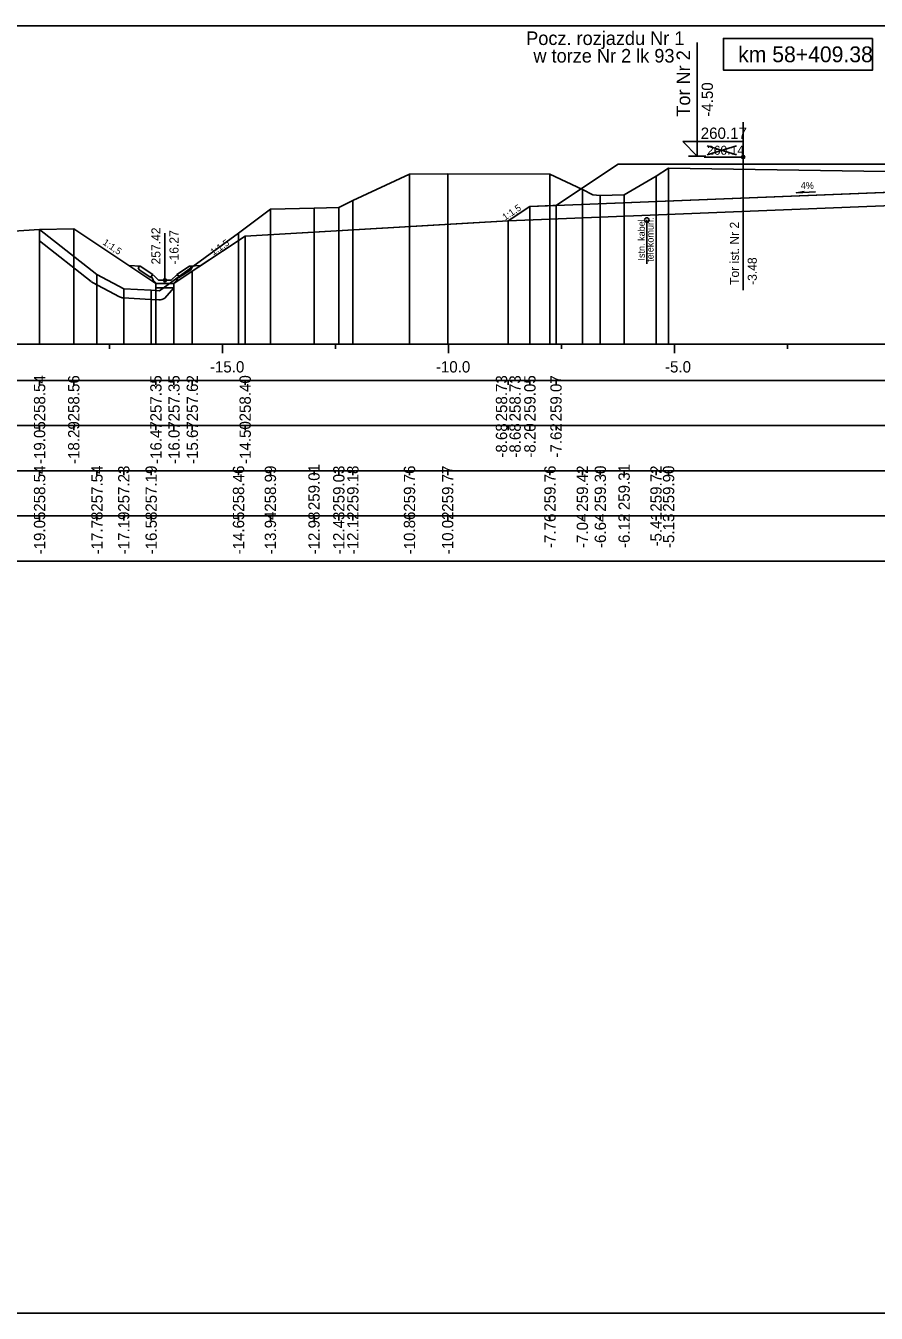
# Model space of a CAD drawing. Extents: x 6516023 to 6560129, y 5513077 to 5529206.
# Drawn here: x 6516540.36 to 6516559.18, y 5514451.16 to 5514479.66 of the extents above; entities that cross this region are included whole.
import ezdxf

# ---------------------------------------------------------------- set-up
doc = ezdxf.new("R2010")
doc.units = 0
for name, color, linetype in [('IR_default', 7, 'Continuous'), ('TOR_PRZEK_P-kable', 7, 'Continuous'), ('TOR_PRZEK_P-komponent', 7, 'Continuous'), ('TOR_PRZEK_P-odwodnienie', 7, 'Continuous'), ('TOR_PRZEK_P-opisy', 7, 'Continuous'), ('TOR_PRZEK_P-schodkowanie+wymiana', 7, 'Continuous'), ('TOR_PRZEK_P-tabelka istniejace', 7, 'Continuous'), ('TOR_PRZEK_P-tabelka projektowane', 7, 'Continuous'), ('TOR_PRZEK_P-teren istniejacy', 7, 'Continuous'), ('TOR_PRZEK_P-tory istniejace', 7, 'Continuous'), ('TOR_PRZEK_P-tory projektowane', 7, 'Continuous'), ('TOR_PRZEK_P-uklad odniesienia', 7, 'Continuous'), ('TOR_PRZEK_P-warstwa ochronna I', 7, 'Continuous'), ('TOR_PRZEK_P-warstwa ochronna II', 7, 'Continuous'), ('TOR_RAMKI-ramka+tabelka 1', 7, 'Continuous')]:
    doc.layers.add(name, color=color, linetype=linetype)

msp = doc.modelspace()

# ---------------------------------------------------------------- linework, layer by layer
at = {"layer": 'IR_default'}
msp.add_lwpolyline([(6516540.664, 5514475.149), (6516541.42, 5514475.164), (6516543.238, 5514473.952), (6516543.288, 5514473.952), (6516543.638, 5514473.952), (6516543.688, 5514473.985), (6516544.043, 5514474.222), (6516544.19, 5514474.32), (6516545.213, 5514475.002), (6516550.135, 5514475.283), (6516551.034, 5514475.335), (6516551.434, 5514475.601), (6516551.513, 5514475.654), (6516552.019, 5514475.674), (6516552.091, 5514475.677), (6516553.293, 5514476.479), (6516553.463, 5514476.592), (6516554.073, 5514476.592), (6516554.159, 5514476.592), (6516555.082, 5514476.592), (6516555.213, 5514476.592), (6516556.746, 5514476.592), (6516556.963, 5514476.592), (6516557.839, 5514476.592), (6516557.963, 5514476.592), (6516559.496, 5514476.592)], dxfattribs=at)
at = {"layer": 'TOR_PRZEK_P-kable'}
msp.add_line((6516554.101, 5514475.357), (6516554.101, 5514474.383), dxfattribs=at)
msp.add_circle((6516554.101, 5514475.357), 0.05, dxfattribs=at)
at = {"layer": 'TOR_PRZEK_P-komponent'}
msp.add_lwpolyline([(6516553.463, 5514476.592), (6516555.213, 5514476.592), (6516554.159, 5514476.592), (6516556.963, 5514476.592), (6516557.963, 5514476.592), (6516559.713, 5514476.592), (6516561.463, 5514476.592), (6516562.013, 5514476.593), (6516563.763, 5514476.593), (6516565.513, 5514476.593), (6516566.063, 5514476.592), (6516569.563, 5514476.592), (6516570.907, 5514475.696), (6516561.738, 5514476.063), (6516552.091, 5514475.677)], close=True, dxfattribs=at)
at = {"layer": 'TOR_PRZEK_P-odwodnienie'}
for p, q in [((6516543.438, 5514474.022), (6516543.438, 5514475.066)), ((6516543.129, 5514474.081), (6516542.868, 5514474.255)), ((6516543.173, 5514474.148), (6516542.893, 5514474.335)), ((6516543.131, 5514474.117), (6516543.178, 5514474.141)), ((6516543.173, 5514474.148), (6516543.165, 5514474.135)), ((6516543.298, 5514474.022), (6516543.178, 5514474.141)), ((6516543.578, 5514474.022), (6516543.698, 5514474.141)), ((6516543.698, 5514474.141), (6516543.746, 5514474.117)), ((6516543.703, 5514474.148), (6516543.983, 5514474.335)), ((6516543.703, 5514474.148), (6516543.711, 5514474.135)), ((6516543.747, 5514474.081), (6516544.008, 5514474.255)), ((6516543.14, 5514474.098), (6516543.129, 5514474.081)), ((6516543.248, 5514473.952), (6516543.628, 5514473.952)), ((6516543.298, 5514474.022), (6516543.578, 5514474.022)), ((6516543.736, 5514474.098), (6516543.747, 5514474.081))]:
    msp.add_line(p, q, dxfattribs=at)
for points in [[(6516542.647, 5514474.346), (6516542.893, 5514474.335)], [(6516542.843, 5514474.308), (6516542.893, 5514474.335)], [(6516542.843, 5514474.308), (6516542.868, 5514474.255)], [(6516543.165, 5514474.135), (6516543.13, 5514474.117)], [(6516543.711, 5514474.135), (6516543.746, 5514474.117)], [(6516544.23, 5514474.346), (6516543.983, 5514474.335)], [(6516544.033, 5514474.308), (6516543.983, 5514474.335)], [(6516544.033, 5514474.308), (6516544.008, 5514474.255)], [(6516543.13, 5514474.117), (6516543.14, 5514474.098)], [(6516543.178, 5514474.022), (6516543.131, 5514474.117)], [(6516543.248, 5514473.952), (6516543.178, 5514474.022)], [(6516543.238, 5514473.952), (6516543.238, 5514473.952), (6516543.238, 5514473.952), (6516543.238, 5514473.951), (6516543.238, 5514473.952), (6516543.239, 5514473.951), (6516543.238, 5514473.952), (6516543.239, 5514473.952)], [(6516543.638, 5514473.952), (6516543.238, 5514473.952), (6516543.238, 5514473.852), (6516543.638, 5514473.852), (6516543.638, 5514473.952)], [(6516543.628, 5514473.952), (6516543.698, 5514474.022)], [(6516543.638, 5514473.952), (6516543.638, 5514473.952), (6516543.638, 5514473.952), (6516543.638, 5514473.951), (6516543.638, 5514473.952), (6516543.639, 5514473.951), (6516543.638, 5514473.952), (6516543.639, 5514473.952)], [(6516543.698, 5514474.022), (6516543.746, 5514474.117)], [(6516543.746, 5514474.117), (6516543.736, 5514474.098)]]:
    msp.add_lwpolyline(points, dxfattribs=at)
msp.add_circle((6516543.438, 5514474.022), 0.035, dxfattribs=at)
at = {"layer": 'TOR_PRZEK_P-opisy'}
msp.add_lwpolyline([(6516557.829, 5514475.979), (6516557.411, 5514475.959), (6516557.579, 5514475.988)], dxfattribs=at)
at = {"layer": 'TOR_PRZEK_P-schodkowanie+wymiana'}
for p, q in [((6516541.838, 5514473.975), (6516542.432, 5514473.655)), ((6516543.432, 5514473.627), (6516543.638, 5514473.852))]:
    msp.add_line(p, q, dxfattribs=at)
for points in [[(6516540.664, 5514474.894), (6516541.809, 5514473.994)], [(6516542.516, 5514473.631), (6516543.122, 5514473.6), (6516543.302, 5514473.589)]]:
    msp.add_lwpolyline(points, dxfattribs=at)
for centre, start, end in [((6516541.933, 5514474.151), 231.8116, 241.7128), ((6516542.527, 5514473.831), 241.7128, 267.0339), ((6516543.315, 5514473.789), 266.4533, 306.0487)]:
    msp.add_arc(centre, 0.2, start, end, dxfattribs=at)
at = {"layer": 'TOR_PRZEK_P-tabelka istniejace'}
for p, q in [((6516540.664, 5514469.706), (6516540.664, 5514469.806)), ((6516541.933, 5514469.706), (6516541.933, 5514469.806)), ((6516542.527, 5514469.706), (6516542.527, 5514469.806)), ((6516543.133, 5514469.706), (6516543.133, 5514469.806)), ((6516545.066, 5514469.706), (6516545.066, 5514469.806)), ((6516545.771, 5514469.706), (6516545.771, 5514469.806)), ((6516546.736, 5514469.706), (6516546.736, 5514469.806)), ((6516547.285, 5514469.706), (6516547.285, 5514469.806)), ((6516547.595, 5514469.706), (6516547.595, 5514469.806)), ((6516548.849, 5514469.706), (6516548.849, 5514469.806)), ((6516549.694, 5514469.706), (6516549.694, 5514469.806)), ((6516551.957, 5514469.706), (6516551.957, 5514469.806)), ((6516552.674, 5514469.706), (6516552.674, 5514469.806)), ((6516553.071, 5514469.706), (6516553.071, 5514469.806)), ((6516553.598, 5514469.706), (6516553.598, 5514469.806)), ((6516554.304, 5514469.706), (6516554.304, 5514469.806)), ((6516554.582, 5514469.706), (6516554.582, 5514469.806)), ((6516518.663, 5514468.806), (6516597.463, 5514468.806)), ((6516540.664, 5514468.706), (6516540.664, 5514468.806)), ((6516541.933, 5514468.706), (6516541.933, 5514468.806)), ((6516542.527, 5514468.706), (6516542.527, 5514468.806)), ((6516543.133, 5514468.706), (6516543.133, 5514468.806)), ((6516545.066, 5514468.706), (6516545.066, 5514468.806)), ((6516545.771, 5514468.706), (6516545.771, 5514468.806)), ((6516546.736, 5514468.706), (6516546.736, 5514468.806)), ((6516547.285, 5514468.706), (6516547.285, 5514468.806)), ((6516547.595, 5514468.706), (6516547.595, 5514468.806)), ((6516548.849, 5514468.706), (6516548.849, 5514468.806)), ((6516549.694, 5514468.706), (6516549.694, 5514468.806)), ((6516551.957, 5514468.706), (6516551.957, 5514468.806)), ((6516552.674, 5514468.706), (6516552.674, 5514468.806)), ((6516553.071, 5514468.706), (6516553.071, 5514468.806)), ((6516553.598, 5514468.706), (6516553.598, 5514468.806)), ((6516554.304, 5514468.706), (6516554.304, 5514468.806)), ((6516554.582, 5514468.706), (6516554.582, 5514468.806))]:
    msp.add_line(p, q, dxfattribs=at)
for points in [[(6516554.582, 5514476.505), (6516554.582, 5514472.806), (6516554.582, 5514472.676), (6516554.582, 5514472.606)], [(6516548.849, 5514476.37), (6516548.849, 5514472.806), (6516548.849, 5514472.676), (6516548.849, 5514472.606)], [(6516549.694, 5514476.376), (6516549.694, 5514472.806), (6516549.694, 5514472.676), (6516549.694, 5514472.606)], [(6516551.957, 5514476.371), (6516551.957, 5514472.806), (6516551.957, 5514472.676), (6516551.957, 5514472.606)], [(6516554.304, 5514476.326), (6516554.304, 5514472.806), (6516554.304, 5514472.676), (6516554.304, 5514472.606)], [(6516552.674, 5514476.03), (6516552.674, 5514472.806), (6516552.674, 5514472.676), (6516552.674, 5514472.606)], [(6516553.071, 5514475.902), (6516553.071, 5514472.806), (6516553.071, 5514472.676), (6516553.071, 5514472.606)], [(6516553.598, 5514475.914), (6516553.598, 5514472.806), (6516553.598, 5514472.676), (6516553.598, 5514472.606)], [(6516545.771, 5514475.594), (6516545.771, 5514472.806), (6516545.771, 5514472.676), (6516545.771, 5514472.606)], [(6516546.736, 5514475.618), (6516546.736, 5514472.806), (6516546.736, 5514472.676), (6516546.736, 5514472.606)], [(6516547.285, 5514475.636), (6516547.285, 5514472.806), (6516547.285, 5514472.676), (6516547.285, 5514472.606)], [(6516547.595, 5514475.787), (6516547.595, 5514472.806), (6516547.595, 5514472.676), (6516547.595, 5514472.606)], [(6516540.664, 5514475.149), (6516540.664, 5514472.806), (6516540.664, 5514472.676), (6516540.664, 5514472.606)], [(6516545.066, 5514475.063), (6516545.066, 5514472.806), (6516545.066, 5514472.676), (6516545.066, 5514472.606)], [(6516541.933, 5514474.151), (6516541.933, 5514472.806), (6516541.933, 5514472.676), (6516541.933, 5514472.606)], [(6516542.527, 5514473.831), (6516542.527, 5514472.806), (6516542.527, 5514472.676), (6516542.527, 5514472.606)], [(6516543.133, 5514473.8), (6516543.133, 5514472.806), (6516543.133, 5514472.676), (6516543.133, 5514472.606)]]:
    msp.add_lwpolyline(points, dxfattribs=at)
msp.add_lwpolyline([(6516518.663, 5514469.806), (6516518.663, 5514467.806), (6516597.463, 5514467.806), (6516597.463, 5514469.806)], close=True, dxfattribs=at)
at = {"layer": 'TOR_PRZEK_P-tabelka projektowane'}
for p, q in [((6516540.664, 5514471.706), (6516540.664, 5514471.806)), ((6516541.42, 5514471.706), (6516541.42, 5514471.806)), ((6516543.238, 5514471.706), (6516543.238, 5514471.806)), ((6516543.638, 5514471.706), (6516543.638, 5514471.806)), ((6516544.043, 5514471.706), (6516544.043, 5514471.806)), ((6516545.213, 5514471.706), (6516545.213, 5514471.806)), ((6516551.034, 5514471.706), (6516551.034, 5514471.806)), ((6516551.513, 5514471.706), (6516551.513, 5514471.806)), ((6516552.091, 5514471.706), (6516552.091, 5514471.806)), ((6516518.663, 5514470.806), (6516597.463, 5514470.806)), ((6516540.664, 5514470.706), (6516540.664, 5514470.806)), ((6516541.42, 5514470.706), (6516541.42, 5514470.806)), ((6516543.238, 5514470.706), (6516543.238, 5514470.806)), ((6516543.638, 5514470.706), (6516543.638, 5514470.806)), ((6516544.043, 5514470.706), (6516544.043, 5514470.806)), ((6516545.213, 5514470.706), (6516545.213, 5514470.806)), ((6516551.034, 5514470.706), (6516551.034, 5514470.806)), ((6516551.513, 5514470.706), (6516551.513, 5514470.806)), ((6516552.091, 5514470.706), (6516552.091, 5514470.806))]:
    msp.add_line(p, q, dxfattribs=at)
for points in [[(6516551.513, 5514475.654), (6516551.513, 5514472.806), (6516551.513, 5514472.676), (6516551.513, 5514472.606)], [(6516552.091, 5514475.677), (6516552.091, 5514472.806), (6516552.091, 5514472.676), (6516552.091, 5514472.606)], [(6516551.034, 5514475.335), (6516551.034, 5514472.806), (6516551.034, 5514472.676), (6516551.034, 5514472.606)], [(6516540.664, 5514475.149), (6516540.664, 5514472.806), (6516540.664, 5514472.676), (6516540.664, 5514472.606)], [(6516541.42, 5514475.164), (6516541.42, 5514472.806), (6516541.42, 5514472.676), (6516541.42, 5514472.606)], [(6516545.213, 5514475.002), (6516545.213, 5514472.806), (6516545.213, 5514472.676), (6516545.213, 5514472.606)], [(6516544.043, 5514474.222), (6516544.043, 5514472.806), (6516544.043, 5514472.676), (6516544.043, 5514472.606)], [(6516543.238, 5514473.952), (6516543.238, 5514472.806), (6516543.238, 5514472.676), (6516543.238, 5514472.606)], [(6516543.638, 5514473.952), (6516543.638, 5514472.806), (6516543.638, 5514472.676), (6516543.638, 5514472.606)]]:
    msp.add_lwpolyline(points, dxfattribs=at)
msp.add_lwpolyline([(6516518.663, 5514471.806), (6516518.663, 5514469.806), (6516597.463, 5514469.806), (6516597.463, 5514471.806)], close=True, dxfattribs=at)
at = {"layer": 'TOR_PRZEK_P-teren istniejacy'}
msp.add_lwpolyline([(6516536.169, 5514474.857), (6516540.664, 5514475.149), (6516541.933, 5514474.151), (6516542.527, 5514473.831), (6516543.133, 5514473.8), (6516543.315, 5514473.789), (6516545.066, 5514475.063), (6516545.771, 5514475.594), (6516546.736, 5514475.618), (6516547.285, 5514475.636), (6516547.595, 5514475.787), (6516548.849, 5514476.37), (6516549.694, 5514476.376), (6516551.957, 5514476.371), (6516552.674, 5514476.03), (6516552.906, 5514475.913), (6516553.071, 5514475.902), (6516553.598, 5514475.914), (6516554.304, 5514476.326), (6516554.582, 5514476.505), (6516562.748, 5514476.38)], dxfattribs=at)
at = {"layer": 'TOR_PRZEK_P-tory istniejace'}
for p, q in [((6516556.232, 5514477.525), (6516556.232, 5514473.805)), ((6516555.433, 5514476.797), (6516556.085, 5514477)), ((6516555.433, 5514477), (6516556.085, 5514476.797)), ((6516556.233, 5514476.75), (6516555.367, 5514476.75))]:
    msp.add_line(p, q, dxfattribs=at)
msp.add_circle((6516556.233, 5514476.75), 0.035, dxfattribs=at)
at = {"layer": 'TOR_PRZEK_P-tory projektowane'}
for p, q in [((6516555.213, 5514477.65), (6516555.213, 5514479.282)), ((6516555.213, 5514477.65), (6516555.213, 5514476.772)), ((6516555.213, 5514476.772), (6516554.894, 5514477.091)), ((6516554.894, 5514477.091), (6516556.238, 5514477.091)), ((6516555.021, 5514476.772), (6516555.405, 5514476.772))]:
    msp.add_line(p, q, dxfattribs=at)
at = {"layer": 'TOR_PRZEK_P-uklad odniesienia'}
for p, q in [((6516522.463, 5514472.606), (6516597.463, 5514472.606)), ((6516542.213, 5514472.506), (6516542.213, 5514472.606)), ((6516544.713, 5514472.406), (6516544.713, 5514472.606)), ((6516547.213, 5514472.506), (6516547.213, 5514472.606)), ((6516549.713, 5514472.406), (6516549.713, 5514472.606)), ((6516552.213, 5514472.506), (6516552.213, 5514472.606)), ((6516554.713, 5514472.406), (6516554.713, 5514472.606)), ((6516557.213, 5514472.506), (6516557.213, 5514472.606))]:
    msp.add_line(p, q, dxfattribs=at)
msp.add_lwpolyline([(6516559.094, 5514479.374), (6516555.794, 5514479.374), (6516555.794, 5514478.674), (6516559.094, 5514478.674)], close=True, dxfattribs=at)
at = {"layer": 'TOR_PRZEK_P-warstwa ochronna I'}
msp.add_lwpolyline([(6516551.034, 5514475.335), (6516561.738, 5514475.763), (6516571.992, 5514475.353)], dxfattribs=at)
at = {"layer": 'TOR_PRZEK_P-warstwa ochronna II'}
msp.add_lwpolyline([(6516540.664, 5514475.149), (6516541.42, 5514475.164), (6516543.238, 5514473.952), (6516543.638, 5514473.952), (6516544.043, 5514474.222), (6516545.213, 5514475.002), (6516551.034, 5514475.335), (6516551.513, 5514475.654), (6516552.091, 5514475.677), (6516560.463, 5514476.012), (6516561.738, 5514476.063), (6516563.013, 5514476.013), (6516570.907, 5514475.696), (6516571.513, 5514475.672), (6516571.992, 5514475.353), (6516573.813, 5514475.18), (6516574.956, 5514474.418), (6516575.436, 5514474.098), (6516575.836, 5514474.098), (6516577.202, 5514475.009)], dxfattribs=at)
at = {"layer": 'TOR_RAMKI-ramka+tabelka 1'}
msp.add_lwpolyline([(6516362.013, 5514479.656), (6516609.513, 5514479.656), (6516609.513, 5514451.156), (6516362.013, 5514451.156)], close=True, dxfattribs=at)

# ---------------------------------------------------------------- texts
at = {"layer": 'TOR_PRZEK_P-kable'}
for s, height, p in [('Istn. kabel', 0.14999, (6516554.056, 5514474.459)), ('telekomun.', 0.15, (6516554.25, 5514474.431))]:
    msp.add_text(s, height=height, rotation=90.0511, dxfattribs=at).set_placement(p)
at = {"layer": 'TOR_PRZEK_P-odwodnienie'}
for s, p in [('257.42', (6516543.338, 5514474.372)), ('-16.27', (6516543.738, 5514474.372))]:
    msp.add_text(s, height=0.2, rotation=90, dxfattribs=at).set_placement(p)
at = {"layer": 'TOR_PRZEK_P-opisy'}
for s, rotation, p in [('4%', 0.1515, (6516557.506, 5514476.044)), ('1:1,5', 34.0701, (6516550.966, 5514475.34)), ('1:1,5', 325.9299, (6516542.047, 5514474.827)), ('1:1,5', 34.0701, (6516544.507, 5514474.567))]:
    msp.add_text(s, height=0.15, rotation=rotation, dxfattribs=at).set_placement(p)
at = {"layer": 'TOR_PRZEK_P-tabelka istniejace'}
for s, p in [('258.54', (6516540.789, 5514468.899)), ('257.54', (6516542.058, 5514468.899)), ('257.23', (6516542.652, 5514468.898)), ('257.19', (6516543.258, 5514468.898)), ('258.46', (6516545.191, 5514468.898)), ('258.99', (6516545.896, 5514468.898)), ('259.01', (6516546.861, 5514468.933)), ('259.03', (6516547.41, 5514468.898)), ('259.18', (6516547.72, 5514468.898)), ('259.76', (6516548.974, 5514468.898)), ('259.77', (6516549.819, 5514468.898)), ('259.76', (6516552.082, 5514468.898)), ('259.42', (6516552.799, 5514468.9)), ('259.30', (6516553.196, 5514468.898)), ('259.31', (6516553.723, 5514468.933)), ('259.72', (6516554.429, 5514468.9)), ('259.90', (6516554.707, 5514468.898)), ('-19.05', (6516540.789, 5514467.953)), ('-17.78', (6516542.058, 5514467.954)), ('-17.19', (6516542.652, 5514467.955)), ('-16.58', (6516543.258, 5514467.954)), ('-14.65', (6516545.191, 5514467.953)), ('-13.94', (6516545.896, 5514467.955)), ('-12.98', (6516546.861, 5514467.954)), ('-12.43', (6516547.41, 5514467.954)), ('-12.12', (6516547.72, 5514467.956)), ('-10.86', (6516548.974, 5514467.954)), ('-10.02', (6516549.819, 5514467.956)), ('-7.76', (6516552.082, 5514468.094)), ('-7.04', (6516552.799, 5514468.095)), ('-6.64', (6516553.196, 5514468.095)), ('-6.12', (6516553.723, 5514468.096)), ('-5.41', (6516554.429, 5514468.129)), ('-5.13', (6516554.707, 5514468.094))]:
    msp.add_text(s, height=0.25, rotation=90, dxfattribs=at).set_placement(p)
at = {"layer": 'TOR_PRZEK_P-tabelka projektowane'}
for s, p in [('258.54', (6516540.789, 5514470.899)), ('258.56', (6516541.545, 5514470.898)), ('257.35', (6516543.363, 5514470.897)), ('257.35', (6516543.763, 5514470.897)), ('257.62', (6516544.168, 5514470.9)), ('258.40', (6516545.338, 5514470.898)), ('258.73', (6516551.01, 5514470.898)), ('258.73', (6516551.31, 5514470.898)), ('259.05', (6516551.638, 5514470.897)), ('259.07', (6516552.216, 5514470.898)), ('-19.05', (6516540.789, 5514469.953)), ('-18.29', (6516541.545, 5514469.955)), ('-16.47', (6516543.363, 5514469.955)), ('-16.07', (6516543.763, 5514469.955)), ('-15.67', (6516544.168, 5514469.955)), ('-14.50', (6516545.338, 5514469.955)), ('-8.68', (6516551.01, 5514470.094)), ('-8.68', (6516551.31, 5514470.094)), ('-8.20', (6516551.638, 5514470.094)), ('-7.62', (6516552.216, 5514470.096))]:
    msp.add_text(s, height=0.25, rotation=90, dxfattribs=at).set_placement(p)
at = {"layer": 'TOR_PRZEK_P-tory istniejace'}
msp.add_text('260.14', height=0.2, dxfattribs=at).set_placement((6516555.433, 5514476.8))
for s, rotation, p in [('Tor ist. Nr 2', 90.0511, (6516556.139, 5514473.92)), ('-3.48', 90, (6516556.533, 5514473.92))]:
    msp.add_text(s, height=0.2, rotation=rotation, dxfattribs=at).set_placement(p)
at = {"layer": 'TOR_PRZEK_P-tory projektowane'}
for s, height, rotation, p in [('Pocz. rozjazdu Nr 1', 0.3, 360, (6516551.431, 5514479.23)), ('w torze Nr 2 lk 93', 0.3, 360, (6516551.591, 5514478.842)), ('Tor Nr 2', 0.3, 90, (6516555.058, 5514477.643)), ('-4.50', 0.25, 90, (6516555.563, 5514477.642))]:
    msp.add_text(s, height=height, rotation=rotation, dxfattribs=at).set_placement(p)
msp.add_text('260.17', height=0.25, dxfattribs=at).set_placement((6516555.293, 5514477.152))
at = {"layer": 'TOR_PRZEK_P-uklad odniesienia'}
for s, height, p in [('km 58+409.38', 0.35, (6516556.122, 5514478.849)), ('-15.0', 0.25, (6516544.432, 5514471.981)), ('-10.0', 0.25, (6516549.432, 5514471.981)), ('-5.0', 0.25, (6516554.502, 5514471.981))]:
    msp.add_text(s, height=height, dxfattribs=at).set_placement(p)

doc.saveas('drawing.dxf')
